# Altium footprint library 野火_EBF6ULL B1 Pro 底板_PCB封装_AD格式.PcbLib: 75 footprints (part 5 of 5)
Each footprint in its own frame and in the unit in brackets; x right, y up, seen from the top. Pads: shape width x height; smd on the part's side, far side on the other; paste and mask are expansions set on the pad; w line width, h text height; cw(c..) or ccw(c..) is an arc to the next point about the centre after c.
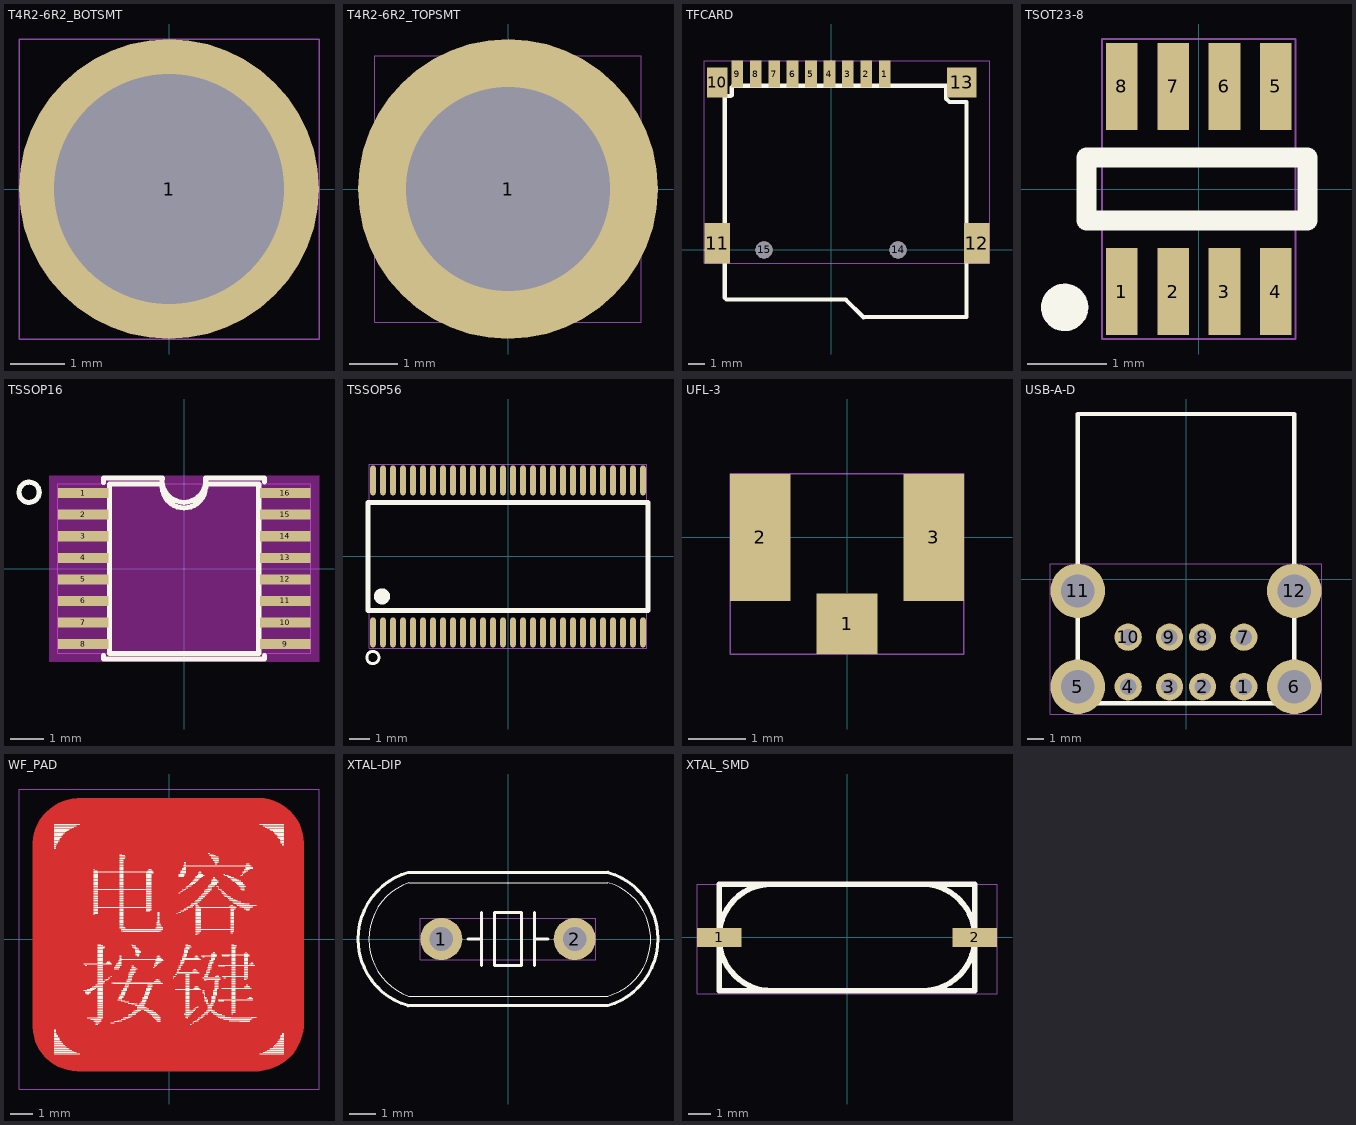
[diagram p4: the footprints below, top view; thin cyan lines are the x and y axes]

## T4R2-6R2_BOTSMT [mil]
pads (1):
  round 216.54 / inner round 216.54 / far side round 244.09 hole 166.14 mask+1.97: 1(0,0)
Top Assembly:
  text "H9" at -39.04,-25 h50
Mechanical 20:
  lines w1: -108.27,-108.27 108.27,-108.27 108.27,108.27 -108.27,108.27 -108.27,-108.27

## T4R2-6R2_TOPSMT [mil]
pads (1):
  round 244.09 / inner round 216.54 / far side round 216.54 hole 166.14 mask+1.97: 1(0,0)
Top Assembly:
  text "H8" at -40.23,-25 h50
Mechanical 20:
  lines w1: -108.27,-108.27 108.27,-108.27 108.27,108.27 -108.27,108.27 -108.27,-108.27

## TFCARD [mil]
pads (15):
  rect 27.56x62.99 smd mask+1.97: 1(125.98,413.39) 2(82.67,413.39) 3(39.37,413.39) 4(-3.94,413.39) 5(-47.25,413.39) 6(-90.55,413.39) 7(-133.86,413.39) 8(-177.17,413.39) 9(-220.48,413.39)
  rect 47.24x70 smd mask+1.97: 10(-267.72,393.7)
  rect 60x95 smd mask+1.97: 11(-267.72,15.75) 12(342.52,15.75)
  rect 70x70 smd mask+1.97: 13(307.08,393.7)
  round 40 hole 40 unplated mask+2.5: 14(157.48,0) 15(-157.48,0)
Top Overlay:
  lines w10: -251.72,361.75 -235.72,361.75 -233.72,363.75 -233.72,381.75 -229.72,385.75 270.28,385.75 270.28,355.75 278.28,347.75 318.28,347.75 318.28,-157.48 76.28,-158.25 34.28,-116.25 -245.72,-116.25 -249.72,-112.25 -249.72,359.75 -251.72,361.75
Top Assembly:
  text "J22" at -57.25,-25 h50
Mechanical 20:
  lines w1: -297.72,-31.75 372.52,-31.75 372.52,444.88 -297.72,444.88 -297.72,-31.75

## TSOT23-8 [mil]
pads (8):
  rect 15.75x43.31 smd mask+2: 1(-38.39,-51.18) 2(-12.8,-51.18) 3(12.8,-51.18) 4(38.39,-51.18) 5(38.39,51.18) 6(12.8,51.18) 7(-12.8,51.18) 8(-38.39,51.18)
Top Overlay:
  circle w11.81: c-66.93,-59.06 r5.91
  lines w10: -56.1,-15.75 -56.1,15.75 54.13,15.75 54.13,-15.75 -56.1,-15.75
Top Assembly:
  text "U25" at 62.49,25 h50
Mechanical 20:
  lines w1: -48.26,-74.83 48.26,-74.83 48.26,74.83 -48.26,74.83 -48.26,-74.83

## TSSOP16 [mil]
height 47
pads (16):
  rect 60x12 smd mask+2: 1(-120,89.6) 2(-120,64) 3(-120,38.4) 4(-120,12.8) 5(-120,-12.8) 6(-120,-38.4) 7(-120,-64) 8(-120,-89.6) 9(120,-89.6) 10(120,-64) 11(120,-38.4) 12(120,-12.8) 13(120,12.8) 14(120,38.4) 15(120,64) 16(120,89.6)
Top Layer keep-out:
  region: -160,-110.5 -160,110.5 160,110.5 160,-110.5
Top Overlay:
  circle w5.98: c-184.02,90.59 r12.02
  lines w6: -95.5,-103 -95.5,-107.5 95.5,-107.5 95.5,-103 ; -95.5,102.5 -95.5,107.5 -26.25,107.5 ; -26,100.5 ccw(c-0.25,97.88) 25.5,100.5 88.5,100.5 88.5,-100.5 -88.5,-100.5 -88.5,100.5 -25.5,100.5 ; -26,107.52 ccw(c-0.25,104.63) 25.5,107.47 ; 25.5,107.5 95.5,107.5 95.5,103
Top Assembly:
  text "U24" at 63.68,25 h50
Mechanical 20:
  lines w1: -150,-100.5 150,-100.5 150,100.5 -150,100.5 -150,-100.5

## TSSOP56 [mil]
pads (56):
  oval 11.02x59.06 smd mask+2: 1(-265.75,-149.61) 2(-246.06,-149.61) 3(-226.38,-149.61) 4(-206.69,-149.61) 5(-187.01,-149.61) 6(-167.32,-149.61) 7(-147.64,-149.61) 8(-127.95,-149.61) 9(-108.27,-149.61) 10(-88.58,-149.61) 11(-68.9,-149.61) 12(-49.21,-149.61) 13(-29.53,-149.61) 14(-9.84,-149.61) 15(9.84,-149.61) 16(29.53,-149.61) 17(49.21,-149.61) 18(68.9,-149.61) 19(88.58,-149.61) 20(108.27,-149.61) 21(127.95,-149.61) 22(147.64,-149.61) 23(167.32,-149.61) 24(187.01,-149.61) 25(206.69,-149.61) 26(226.38,-149.61) 27(246.06,-149.61) 28(265.75,-149.61) 29(265.75,149.61) 30(246.06,149.61) 31(226.38,149.61) 32(206.69,149.61) 33(187.01,149.61) 34(167.32,149.61) 35(147.64,149.61) 36(127.95,149.61) 37(108.27,149.61) 38(88.58,149.61) 39(68.9,149.61) 40(49.21,149.61) 41(29.53,149.61) 42(9.84,149.61) 43(-9.84,149.61) 44(-29.53,149.61) 45(-49.21,149.61) 46(-68.9,149.61) 47(-88.58,149.61) 48(-108.27,149.61) 49(-127.95,149.61) 50(-147.64,149.61) 51(-167.32,149.61) 52(-187.01,149.61) 53(-206.69,149.61) 54(-226.38,149.61) 55(-246.06,149.61) 56(-265.75,149.61)
Top Overlay:
  circle w5.98: c-266.02,-199.01 r12.02
  circle w15.75: c-248.03,-78.74 r7.87
  lines w10: -275.59,-106.3 275.59,-106.3 275.59,106.3 -275.59,106.3 -275.59,-106.3
Top Assembly:
  text "U19" at 57.37,25 h50
Mechanical 20:
  lines w1: -273.26,-181.13 273.26,-181.13 273.26,181.13 -273.26,181.13 -273.26,-181.13

## UFL-3 [mil]
pads (3):
  rect 41.34x41.34 smd mask+1.97: 1(0,-59.06)
  rect 41.34x86.61 smd mask+1.97: 2(-59.06,0) 3(59.06,0)
Top Assembly:
  text "CN7" at 65.11,25 h50
Mechanical 20:
  lines w1: -79.72,-79.72 79.72,-79.72 79.72,43.31 -79.72,43.31 -79.72,-79.72

## USB-A-D [mil]
pads (12):
  round 65 hole 39.37 mask+2.5: 1(137.8,-255.91) 2(39.37,-255.91) 3(-39.37,-255.91) 4(-137.8,-255.91) 7(137.8,-137.8) 8(39.37,-137.8) 9(-39.37,-137.8) 10(-137.8,-137.8)
  round 129.92 hole 78.74 mask+2: 5(-257.87,-255.91) 6(257.87,-255.91) 11(-257.87,-27.56) 12(257.87,-27.56)
Top Overlay:
  lines w10: -257.87,-295.28 257.87,-295.28 257.87,393.7 -257.87,393.7 -257.87,-295.28
Top Assembly:
  text "J36" at 56.06,25 h50
Mechanical 20:
  lines w1: -322.83,-320.87 322.83,-320.87 322.83,37.4 -322.83,37.4 -322.83,-320.87

## WF_PAD [mil]
Top Layer:
  region: -241.18,170.88 -240.24,179.53 -238.41,188.04 -235.7,196.31 -232.15,204.25 -227.79,211.78 -222.67,218.82 -216.85,225.28 -210.38,231.11 -203.35,236.23 -195.82,240.59 -187.87,244.14 -179.6,246.85 -171.1,248.68 -162.44,249.62 159.76,249.62 168.53,249 177.18,247.42 185.6,244.9 193.7,241.47 201.37,237.18 208.53,232.07 215.08,226.2 220.94,219.65 226.05,212.5 230.35,204.83 233.78,196.73 236.3,188.31 237.88,179.66 238.5,170.88 238.5,-155.18 237.47,-163.79 235.56,-172.26 232.8,-180.48 229.21,-188.38 224.83,-195.87 219.7,-202.87 213.89,-209.31 207.45,-215.12 200.45,-220.24 192.96,-224.62 185.07,-228.21 176.84,-230.98 168.38,-232.89 159.76,-233.92 -162.44,-233.92 -171.24,-233.39 -179.93,-231.88 -188.4,-229.42 -196.54,-226.02 -204.25,-221.75 -211.44,-216.64 -218.02,-210.76 -223.9,-204.18 -229.01,-196.99 -233.28,-189.28 -236.68,-181.14 -239.14,-172.67 -240.65,-163.98 -241.18,-155.18
Top Overlay:
  drawing of 867 lines, arcs and shapes, not listed
Top Assembly:
  text "TPAD1" at -94.98,-25 h50
Mechanical 20:
  lines w1: -265.75,-265.75 265.75,-265.75 265.75,265.75 -265.75,265.75 -265.75,-265.75

## XTAL-DIP [mil]
pads (2):
  round 62.99 hole 35.43 mask+2: 1(-100,0) 2(100,0)
Top Overlay:
  lines w1: 149.45,-85.69 ccw(c125.85,-0.59) 149.6,84.47 ; 149.53,-85.67 -148.7,-85.67 cw(c-118.91,-0.59) -148.7,84.49 149.53,84.49
  lines w4.72: -150.08,99.98 ccw(c-120.85,0) -149.91,-100.03 ; -150,-100 150,-100 ; -150,100 150,100 ; -60,0 -40,0 ; -40,-40 -40,40 ; 40,-40 40,40 ; 40,0 60,0 ; 149.91,100.03 cw(c120.85,0) 150.08,-99.98 ; -20,-40 -20,40 20,40 20,-40 -20,-40
Top Assembly:
  text "Y6" at 37.73,25 h50
Mechanical 20:
  lines w1: -131.5,-31.5 131.5,-31.5 131.5,31.5 -131.5,31.5 -131.5,-31.5

## XTAL_SMD [mm]
pads (2):
  rect 2x0.85 smd mask+0.05: 1(-5.75,0) 2(5.75,0)
Top Overlay:
  lines w0.254: -5.75,-0.069 -5.75,0 ; -5.75,-0.068 ccw(c-3.385,-0.035) -3.352,-2.4 ; -5.75,0.002 cw(c-3.385,0.035) -3.418,2.4 ; 3.352,2.4 cw(c3.385,0.035) 5.75,0.068 ; 3.418,-2.4 ccw(c3.385,-0.035) 5.75,-0.002 ; 5.75,0 5.75,0.069 ; -5.75,-2.4 -5.75,2.4 5.75,2.4 5.75,-2.4 -5.75,-2.4
Top Assembly:
  text "Y5" at 0.989,0.635 h1.27
Mechanical 20:
  lines w0.025: -6.75,-2.54 -6.75,2.4 6.75,2.4 6.75,-2.54 -6.75,-2.54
